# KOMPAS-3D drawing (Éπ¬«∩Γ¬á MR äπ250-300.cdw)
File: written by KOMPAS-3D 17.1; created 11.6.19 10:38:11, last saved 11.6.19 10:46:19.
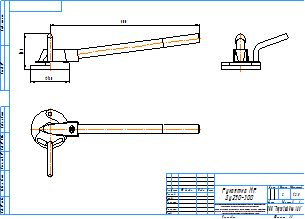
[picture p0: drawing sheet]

Sheet 1: A3, landscape

Title block, sheet 1: name: Рукоятка MR / Ду250-300; material: Сталь 20  ГОСТ 1050-2013; mass: 2; sheets: 1; sheet format: A3; stored path: C:\Users\kka\KOMPAS_Work\!Trash\ГРАНВЭЛ с редукторами приводами\Рукоятка MR Ду250-300.cdw

Views: Вид 1, Проекционный вид 2, Проекционный вид 3
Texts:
  kka
  adl
  Рама для чертежей
  Лит-Масса-Масштаб
  Материал-Предприятие
  Масштаб
  Изм.
  Лист
  № докум.
  Подп.
  Дата
  Лит.
  Разраб.
  Пров.
  Т.контр.
  Листов
  Внимание! Данный продукт является объектом авторского права ООО «Торговый Дом АДЛ».
  Запрещается изменение, копирование, распространение
  (в том числе путем копирования на другие сайты и ресурсы в Интернете)
  или любое иное использование информации и объектов без предварительного
  согласия правообладателя (ООО «Торговый Дом АДЛ»).
  Н.контр.
  Утв.
  ООО "Торговый дом АДЛ"
  Изменение
  Номер документа
  Подпись
  Обозначение документа
  Наименование изделия
  Масса изделия по ГОСТ 2.109-73
  Порядковый номер листа
  Общее количество листов в документе
  Характер работы, выполненной лицом, подписавшим документ
  Наименование или индекс предприятия, выпускающего документ
  Инв. № подл.
  Подп. и дата
  Взам. инв. №
  Инв. № дубл.
  Инвентарный номер подлинника по ГОСТ 2.501-68
  Подпись принявшего подлинник в отдел технической документации
  Инвентарный номер подлинника, взамен которого выпущен данный подлинник
  Инвентарный номер дубликата по ГОСТ 2.502-68
  Подпись принявшего дубликат в отдел технической документации
  Справ. №
  Перв. примен.
  Обозначение документа, взамен или на основании которого выпущен данный документ
  Обозначение документа, в котором впервые записан данный документ
  Подпись лица, копировавшего чертеж
  Обозначение формата листа
  !Рама для чертежа
Dimensions and other numbers on the sheet: 500; 130; 120; 1:2,5; 1; 2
